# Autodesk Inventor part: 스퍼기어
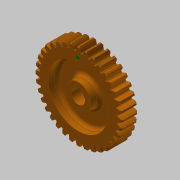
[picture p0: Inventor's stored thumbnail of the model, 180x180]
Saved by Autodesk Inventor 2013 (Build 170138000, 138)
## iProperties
Created: 2019-01
Part Number: 스퍼기어
Material: 알루미늄 6061
Document SubType Name: Modeling
Designer: mduedu
Density: 2.71 g/cm^3
Mass: 116.798 g
Surface Area: 167.013 cm^2
Volume: 43.0987 cm^3
Author: mduedu
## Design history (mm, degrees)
sketch "스케치1"
  geometry: C1 r 33.5 at (0, 0); C2 r 36 at (0, 0); C3 r 38 at (0, 0); 1 further point
  constraints: 3 centre point, 3 coincident
  dimensions: "d0" = 67 diameter of C1; "d2" = 72 diameter of C2; "d3" = 76 diameter of C3
extrude "돌출1" new body sketch "스케치1" distance "d4" = 14; taper "d5" = 0 deg
sketch "스케치2"
  geometry: L1 (0, 0)-(-38, 0); L2 (0, 0)-(0, 38); L3 (-0.57, 0)-(-0.57, 37.996); L4 (-1.57, 0)-(-1.57, 35.966); L5 (-2.07, 0)-(-2.07, 33.436); A1 r 38 centre (0, 0) between (-38, 0) and (0, 38) reference; A2 r 9.246 centre (7.162, 32.926) between (-0.57, 37.996) and (-2.07, 33.436); A3 r 9.246 centre (-7.162, 32.926) between (2.07, 33.436) and (0.57, 37.996); A4 r 33.5 centre (0, 0) between (2.07, 33.436) and (-2.07, 33.436); A5 r 38 centre (0, 0) between (0.57, 37.996) and (-0.57, 37.996); 2 further points
  constraints: 12 point on circle, 10 end point, 4 centre point, 3 parallel, 3 symmetric about line, 2 coincident, 1 horizontal, 1 perpendicular, 5 other
  dimensions: "d6" = 0.5 distance between parallel lines of L4 L5; "d8" = 1 distance between parallel lines of L3 L4; "d9" = 1.57 distance between parallel lines of L2 L4
extrude "돌출2" join sketch "스케치2" stored distance "d10" = 14; taper "d11" = 0 deg
chamfer "모따기1" distance "d12" = 1; stored, may be unused: second distance "d13" = 2, angle "d14" = 45 deg
fillet "모깎기1" dims "d15" = 0.5
sketch "스케치3"
  geometry: C1 r 11 at (0, 0); 1 further point
  constraints: 1 centre point, 1 coincident
  dimensions: "d19" = 22 diameter of C1
extrude "돌출3" join sketch "스케치3" distance "d20" = 7; taper "d21" = 0 deg
fillet "모깎기2" dims "d22" = 3
sketch "스케치4"
  geometry: C1 r 11 at (0, 0); C2 r 26 at (0, 0); 1 further point
  constraints: 2 centre point, 2 coincident
  dimensions: "d23" = 22 diameter of C1; "d24" = 52 diameter of C2
extrude "돌출4" cut sketch "스케치4" distance "d25" = 8; taper "d26" = 0 deg
fillet "모깎기3" dims "d27" = 3
sketch "스케치5" dims "d28" = 60
  geometry: C1 r 1.5 at (0, 30); 2 further points
  constraints: 2 vertical alignment, 1 centre point, 1 coincident, 2 other
  dimensions: "d29" = 3 diameter of C1
extrude "돌출5" join sketch "스케치5" distance "d30" = 0.5; taper "d31" = 0 deg
sketch "스케치6"
  geometry: L1 (-2, 5.657)-(2, 5.657); L2 (2, 5.657)-(2, 7.8); L3 (2, 7.8)-(-2, 7.8); L4 (-2, 7.8)-(-2, 5.657); A1 r 6 centre (0, 0) between (-2, 5.657) and (2, 5.657); 1 further point
  constraints: 8 end point, 2 parallel, 2 point on circle, 1 centre point, 1 coincident, 1 horizontal, 1 perpendicular
  dimensions: "d32" = 13.8 dimension on A1 L3; "d34" = 4 distance of L2.end L3.end; "d35" = 12 diameter of A1
extrude "돌출6" cut sketch "스케치6" stored distance "d36" = 0.5; taper "d37" = 0 deg
chamfer "모따기2" distance "d38" = 1; stored, may be unused: second distance "d39" = 2, angle "d40" = 45 deg
node "솔리드1"
pattern_circular "원형 패턴1" dims "d17" = 360 deg
